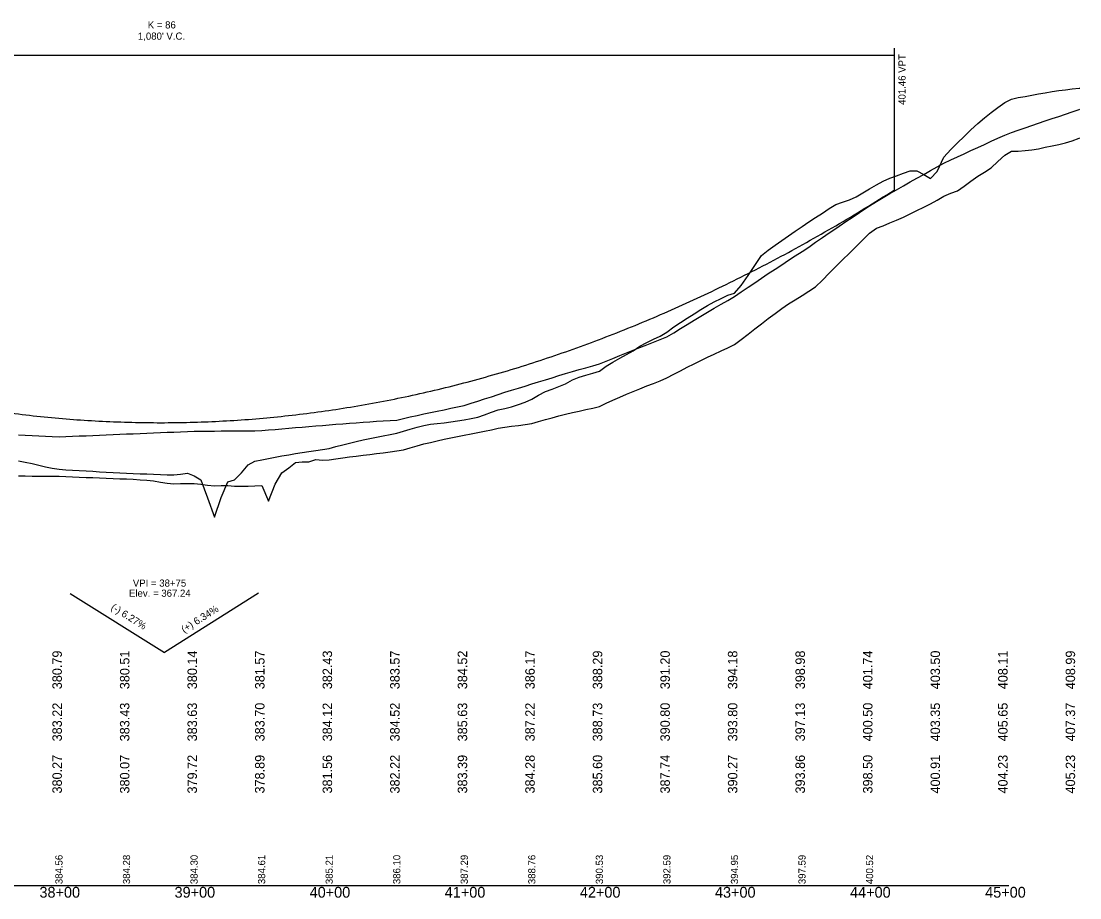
# Model space of a CAD drawing. Extents: x 2116146 to 2121546, y 979095 to 984095.
# Drawn here: x 2119138 to 2119922, y 981586 to 982235 of the extents above; entities that cross this region are included whole.
import ezdxf

# ---------------------------------------------------------------- set-up
doc = ezdxf.new("R2010")
doc.units = 0
for name, color, linetype in [('RD_DDB_GradeTX', 7, 'Continuous'), ('RD_DDB_Profile_EX', 7, 'Continuous'), ('RD_DDB_Profile_Lbl', 7, 'Continuous'), ('RD_DDB_Profile_PR', 7, 'Continuous'), ('RD_DDB_StaTX', 7, 'Continuous'), ('RD_DDB_StripGrade', 7, 'Continuous'), ('RD_DDB_VCLbl', 7, 'Continuous'), ('RD_GPK_Profile_Cell', 7, 'Continuous'), ('RD_Sketch2', 7, 'Continuous')]:
    doc.layers.add(name, color=color, linetype=linetype)

msp = doc.modelspace()

# ---------------------------------------------------------------- linework, layer by layer
at = {"layer": 'RD_DDB_GradeTX'}
for p in [(2119174.3, 981811.6), (2119313.72, 981811.95)]:
    msp.add_line(p, (2119244.12, 981767.84), dxfattribs=at)
at = {"layer": 'RD_DDB_Profile_EX'}
for points in [[(2119756.02, 982091.92), (2119761.02, 982095.22), (2119766.02, 982098.49), (2119771.02, 982101.66), (2119776.02, 982104.66), (2119781.02, 982107.56), (2119786.02, 982110.45), (2119791.02, 982113.32), (2119796.02, 982116.17), (2119801.02, 982118.99), (2119806.02, 982121.77), (2119811.02, 982124.56), (2119816.02, 982127.34), (2119821.02, 982130.05), (2119826.02, 982132.44), (2119831.02, 982134.77), (2119836.02, 982137.07), (2119841.02, 982139.36), (2119846.02, 982141.65), (2119851.02, 982144), (2119856.02, 982146.27), (2119861.02, 982148.49), (2119866.02, 982150.69), (2119871.02, 982152.8), (2119876.02, 982154.49), (2119881.02, 982156.22), (2119886.02, 982158.01), (2119891.02, 982159.79), (2119896.02, 982161.52), (2119901.02, 982163.11), (2119906.02, 982164.71), (2119911.02, 982166.42), (2119916.02, 982168.11), (2119921.02, 982169.77), (2119921.6, 982169.95)], [(2119256.02, 981931.31), (2119261.02, 981931.52), (2119266.02, 981931.74), (2119271.02, 981931.77), (2119276.02, 981931.8), (2119281.02, 981931.83), (2119286.02, 981931.87), (2119291.02, 981931.95), (2119296.02, 981931.98), (2119301.02, 981932.01), (2119306.02, 981932.03), (2119311.02, 981932.06), (2119316.02, 981932.15), (2119321.02, 981932.62), (2119326.02, 981933.09), (2119331.02, 981933.55), (2119336.02, 981934), (2119341.02, 981934.41), (2119346.02, 981934.75), (2119351.02, 981935.15), (2119356.02, 981935.56), (2119361.02, 981935.95), (2119366.02, 981936.36), (2119371.02, 981936.87), (2119376.02, 981937.24), (2119381.02, 981937.59), (2119386.02, 981937.94), (2119391.02, 981938.31), (2119396.02, 981938.76), (2119401.02, 981939.06), (2119406.02, 981939.35), (2119411.02, 981939.62), (2119416.02, 981939.98), (2119421.02, 981941.13), (2119426.02, 981942.26), (2119431.02, 981943.39), (2119436.02, 981944.5), (2119441.02, 981945.49), (2119446.02, 981946.57), (2119451.02, 981947.64), (2119456.02, 981948.7), (2119461.02, 981949.75), (2119466.02, 981950.71), (2119471.02, 981952.41), (2119476.02, 981954.03), (2119481.02, 981955.64), (2119486.02, 981957.24), (2119491.02, 981958.83), (2119496.02, 981960.48), (2119501.02, 981962.04), (2119506.02, 981963.59), (2119511.02, 981965.13), (2119516.02, 981966.67), (2119521.02, 981968.31), (2119526.02, 981969.82), (2119531.02, 981971.32), (2119536.02, 981972.81), (2119541.02, 981974.29), (2119546.02, 981975.84), (2119551.02, 981977.28), (2119556.02, 981978.7), (2119561.02, 981980.1), (2119566.02, 981981.49), (2119571.02, 981983.53), (2119576.02, 981985.6), (2119581.02, 981987.64), (2119586.02, 981989.67), (2119591.02, 981991.68), (2119596.02, 981993.67), (2119601.02, 981995.64), (2119606.02, 981997.6), (2119611.02, 981999.51), (2119616.02, 982001.53), (2119621.02, 982004.63), (2119626.02, 982007.7), (2119631.02, 982010.75), (2119636.02, 982013.78), (2119641.02, 982016.77), (2119646.02, 982019.75), (2119651.02, 982022.71), (2119656.02, 982025.65), (2119661.02, 982028.56), (2119666.02, 982031.41), (2119671.02, 982034.8), (2119676.02, 982038.23), (2119681.02, 982041.63), (2119686.02, 982045), (2119691.02, 982048.35), (2119696.02, 982051.62), (2119701.02, 982054.91), (2119706.02, 982058.18), (2119711.02, 982061.42), (2119716.02, 982064.63), (2119721.02, 982068.02), (2119726.02, 982071.52), (2119731.02, 982074.99), (2119736.02, 982078.43), (2119741.02, 982081.84), (2119746.02, 982085.23), (2119751.02, 982088.59), (2119756.02, 982091.92)], [(2119136.02, 981928.95), (2119141.02, 981928.7), (2119146.02, 981928.45), (2119151.02, 981928.2), (2119156.02, 981927.94), (2119161.02, 981927.69), (2119166.02, 981927.58), (2119171.02, 981927.78), (2119176.02, 981927.98), (2119181.02, 981928.19), (2119186.02, 981928.39), (2119191.02, 981928.61), (2119196.02, 981928.81), (2119201.02, 981929.01), (2119206.02, 981929.22), (2119211.02, 981929.42), (2119216.02, 981929.64), (2119221.02, 981929.85), (2119226.02, 981930.05), (2119231.02, 981930.26), (2119236.02, 981930.47), (2119241.02, 981930.69), (2119246.02, 981930.9), (2119251.02, 981931.1), (2119256.02, 981931.31)]]:
    msp.add_lwpolyline(points, dxfattribs=at)
at = {"layer": 'RD_DDB_Profile_PR'}
msp.add_spline([(2118704.12, 982106.3), (2118725.72, 982093.03), (2118747.32, 982080.31), (2118768.92, 982068.13), (2118790.52, 982056.5), (2118812.12, 982045.41), (2118833.72, 982034.87), (2118855.32, 982024.87), (2118876.92, 982015.42), (2118898.52, 982006.51), (2118920.12, 981998.14), (2118941.72, 981990.32), (2118963.32, 981983.05), (2118984.92, 981976.32), (2119006.52, 981970.13), (2119028.12, 981964.49), (2119049.72, 981959.39), (2119071.32, 981954.84), (2119092.92, 981950.83), (2119114.52, 981947.37), (2119136.12, 981944.45), (2119157.72, 981942.07), (2119179.32, 981940.24), (2119200.92, 981938.96), (2119222.52, 981938.22), (2119244.12, 981938.02), (2119265.72, 981938.37), (2119287.32, 981939.26), (2119308.92, 981940.7), (2119330.52, 981942.68), (2119352.12, 981945.21), (2119373.72, 981948.28), (2119395.32, 981951.89), (2119416.92, 981956.05), (2119438.52, 981960.76), (2119460.12, 981966.01), (2119481.72, 981971.8), (2119503.32, 981978.14), (2119524.92, 981985.03), (2119546.52, 981992.45), (2119568.12, 982000.43), (2119589.72, 982008.94), (2119611.32, 982018), (2119632.92, 982027.61), (2119654.52, 982037.76), (2119676.12, 982048.46), (2119697.72, 982059.7), (2119719.32, 982071.48), (2119740.92, 982083.81), (2119762.52, 982096.68), (2119784.12, 982110.1)], degree=3, dxfattribs=at)
at = {"layer": 'RD_DDB_VCLbl'}
for p, q in [((2119784.12, 982215.1), (2119784.12, 982110.1)), ((2118704.12, 982210.1), (2119784.12, 982210.1))]:
    msp.add_line(p, q, dxfattribs=at)
at = {"layer": 'RD_GPK_Profile_Cell'}
msp.add_line((2117569.12, 981595.48), (2119869.12, 981595.48), dxfattribs=at)
at = {"layer": 'RD_Sketch2'}
for points in [[(2119756.02, 982105.09), (2119761.02, 982108.15), (2119766.02, 982111.08), (2119771.02, 982113.99), (2119776.02, 982116.88), (2119781.02, 982119.01), (2119786.02, 982120.82), (2119791.02, 982122.68), (2119796.02, 982124.51), (2119801.02, 982124.49), (2119806.02, 982121.78), (2119811.02, 982118.63), (2119816.02, 982124.03), (2119821.02, 982134.49), (2119826.02, 982140.12), (2119831.02, 982145.1), (2119836.02, 982149.9), (2119841.02, 982154.79), (2119846.02, 982159.53), (2119851.02, 982163.63), (2119856.02, 982167.56), (2119861.02, 982171.31), (2119866.02, 982174.89), (2119871.02, 982177.54), (2119876.02, 982178.56), (2119881.02, 982179.52), (2119886.02, 982180.42), (2119891.02, 982181.27), (2119896.02, 982182.2), (2119901.02, 982183.06), (2119906.02, 982183.77), (2119911.02, 982184.42), (2119916.02, 982185.01), (2119921.02, 982185.54), (2119921.52, 982185.58)], [(2119756.02, 982068.43), (2119761.02, 982073.35), (2119766.02, 982078.22), (2119771.02, 982081.9), (2119776.02, 982083.82), (2119781.02, 982085.81), (2119786.02, 982087.87), (2119791.02, 982090.22), (2119796.02, 982092.67), (2119801.02, 982095.02), (2119806.02, 982097.44), (2119811.02, 982099.93), (2119816.02, 982102.77), (2119821.02, 982105.62), (2119826.02, 982107.76), (2119831.02, 982109.72), (2119836.02, 982113.15), (2119841.02, 982116.81), (2119846.02, 982120.56), (2119851.02, 982123.43), (2119856.02, 982126.69), (2119861.02, 982131.22), (2119866.02, 982135.9), (2119871.02, 982138.88), (2119876.02, 982139.05), (2119881.02, 982139.37), (2119886.02, 982139.84), (2119891.02, 982140.6), (2119896.02, 982141.96), (2119901.02, 982142.89), (2119906.02, 982143.94), (2119911.02, 982145.1), (2119916.02, 982146.58), (2119921.02, 982148.59), (2119921.6, 982148.78)], [(2119256.02, 981899.83), (2119261.02, 981900.68), (2119266.02, 981898.75), (2119271.02, 981895.8), (2119276.02, 981882.44), (2119281.02, 981868.19), (2119286.02, 981882.57), (2119291.02, 981894.21), (2119296.02, 981895.65), (2119301.02, 981900.82), (2119306.02, 981906.79), (2119311.02, 981909.64), (2119316.02, 981910.6), (2119321.02, 981911.6), (2119326.02, 981912.57), (2119331.02, 981913.47), (2119336.02, 981914.31), (2119341.02, 981915.15), (2119346.02, 981916), (2119351.02, 981916.79), (2119356.02, 981917.5), (2119361.02, 981918.18), (2119366.02, 981918.96), (2119371.02, 981920.28), (2119376.02, 981921.56), (2119381.02, 981922.82), (2119386.02, 981924.06), (2119391.02, 981925.2), (2119396.02, 981926.23), (2119401.02, 981927.26), (2119406.02, 981928.29), (2119411.02, 981929.3), (2119416.02, 981930.34), (2119421.02, 981931.76), (2119426.02, 981933.18), (2119431.02, 981934.6), (2119436.02, 981936.01), (2119441.02, 981936.8), (2119446.02, 981937.44), (2119451.02, 981938.01), (2119456.02, 981938.53), (2119461.02, 981939.3), (2119466.02, 981940.03), (2119471.02, 981941.15), (2119476.02, 981942.21), (2119481.02, 981943.92), (2119486.02, 981945.85), (2119491.02, 981947.56), (2119496.02, 981948.57), (2119501.02, 981949.67), (2119506.02, 981951.47), (2119511.02, 981953.25), (2119516.02, 981955.31), (2119521.02, 981958.33), (2119526.02, 981960.97), (2119531.02, 981962.86), (2119536.02, 981964.7), (2119541.02, 981966.87), (2119546.02, 981969.68), (2119551.02, 981971.62), (2119556.02, 981973.15), (2119561.02, 981974.6), (2119566.02, 981976.11), (2119571.02, 981979.75), (2119576.02, 981982.91), (2119581.02, 981985.75), (2119586.02, 981988.51), (2119591.02, 981991.26), (2119596.02, 981994.64), (2119601.02, 981997.42), (2119606.02, 981999.78), (2119611.02, 982002.03), (2119616.02, 982004.98), (2119621.02, 982008.93), (2119626.02, 982012.24), (2119631.02, 982015.44), (2119636.02, 982018.5), (2119641.02, 982021.76), (2119646.02, 982024.77), (2119651.02, 982027.43), (2119656.02, 982029.96), (2119661.02, 982032.36), (2119666.02, 982033.83), (2119671.02, 982039.44), (2119676.02, 982046.85), (2119681.02, 982054.27), (2119686.02, 982061.67), (2119691.02, 982065.74), (2119696.02, 982069.29), (2119701.02, 982072.82), (2119706.02, 982076.32), (2119711.02, 982079.79), (2119716.02, 982083.23), (2119721.02, 982086.58), (2119726.02, 982089.88), (2119731.02, 982093.16), (2119736.02, 982096.41), (2119741.02, 982099.61), (2119746.02, 982101.29), (2119751.02, 982102.96), (2119756.02, 982105.09)], [(2119256.02, 981892.95), (2119261.02, 981893.09), (2119266.02, 981893.07), (2119271.02, 981892.39), (2119276.02, 981891.71), (2119281.02, 981891.38), (2119286.02, 981891.52), (2119291.02, 981891.55), (2119296.02, 981891.13), (2119301.02, 981890.91), (2119306.02, 981891.09), (2119311.02, 981891.27), (2119316.02, 981891.44), (2119321.02, 981879.98), (2119326.02, 981892.53), (2119331.02, 981900.8), (2119336.02, 981904.62), (2119341.02, 981908.44), (2119346.02, 981909.04), (2119351.02, 981909.16), (2119356.02, 981910.88), (2119361.02, 981910.36), (2119366.02, 981910.64), (2119371.02, 981911.32), (2119376.02, 981911.98), (2119381.02, 981912.63), (2119386.02, 981913.28), (2119391.02, 981913.95), (2119396.02, 981914.57), (2119401.02, 981915.19), (2119406.02, 981915.8), (2119411.02, 981916.41), (2119416.02, 981917.11), (2119421.02, 981917.99), (2119426.02, 981919.47), (2119431.02, 981920.91), (2119436.02, 981922.27), (2119441.02, 981923.35), (2119446.02, 981924.58), (2119451.02, 981925.76), (2119456.02, 981926.89), (2119461.02, 981927.85), (2119466.02, 981928.75), (2119471.02, 981929.75), (2119476.02, 981930.71), (2119481.02, 981931.63), (2119486.02, 981932.67), (2119491.02, 981934.01), (2119496.02, 981934.74), (2119501.02, 981935.4), (2119506.02, 981936.02), (2119511.02, 981936.58), (2119516.02, 981937.35), (2119521.02, 981938.87), (2119526.02, 981940.32), (2119531.02, 981941.72), (2119536.02, 981943.05), (2119541.02, 981944.31), (2119546.02, 981945.51), (2119551.02, 981946.64), (2119556.02, 981947.71), (2119561.02, 981948.72), (2119566.02, 981949.98), (2119571.02, 981952.35), (2119576.02, 981954.66), (2119581.02, 981956.9), (2119586.02, 981959.08), (2119591.02, 981961.11), (2119596.02, 981963.17), (2119601.02, 981965.18), (2119606.02, 981967.11), (2119611.02, 981968.99), (2119616.02, 981971.21), (2119621.02, 981973.88), (2119626.02, 981976.5), (2119631.02, 981979.06), (2119636.02, 981981.56), (2119641.02, 981984.05), (2119646.02, 981986.42), (2119651.02, 981988.72), (2119656.02, 981991.09), (2119661.02, 981993.51), (2119666.02, 981995.97), (2119671.02, 981999.51), (2119676.02, 982003.48), (2119681.02, 982007.38), (2119686.02, 982011.23), (2119691.02, 982015.02), (2119696.02, 982018.75), (2119701.02, 982022.41), (2119706.02, 982026.02), (2119711.02, 982029.04), (2119716.02, 982032.02), (2119721.02, 982035.37), (2119726.02, 982038.67), (2119731.02, 982043.52), (2119736.02, 982048.57), (2119741.02, 982053.59), (2119746.02, 982058.58), (2119751.02, 982063.55), (2119756.02, 982068.43)], [(2119136.02, 981909.85), (2119141.02, 981908.82), (2119146.02, 981907.69), (2119151.02, 981906.57), (2119156.02, 981905.44), (2119161.02, 981904.43), (2119166.02, 981903.6), (2119171.02, 981903.22), (2119176.02, 981902.83), (2119181.02, 981902.56), (2119186.02, 981902.33), (2119191.02, 981902.06), (2119196.02, 981901.69), (2119201.02, 981901.4), (2119206.02, 981901.19), (2119211.02, 981900.98), (2119216.02, 981900.74), (2119221.02, 981900.42), (2119226.02, 981900.24), (2119231.02, 981900.05), (2119236.02, 981899.87), (2119241.02, 981899.65), (2119246.02, 981899.47), (2119251.02, 981899.31), (2119256.02, 981899.83)], [(2119136.02, 981898.68), (2119141.02, 981898.71), (2119146.02, 981898.43), (2119151.02, 981898.32), (2119156.02, 981898.35), (2119161.02, 981898.38), (2119166.02, 981898.33), (2119171.02, 981898.1), (2119176.02, 981897.87), (2119181.02, 981897.64), (2119186.02, 981897.47), (2119191.02, 981897.46), (2119196.02, 981897.21), (2119201.02, 981896.96), (2119206.02, 981896.7), (2119211.02, 981896.45), (2119216.02, 981896.37), (2119221.02, 981896.09), (2119226.02, 981895.81), (2119231.02, 981895.53), (2119236.02, 981895.02), (2119241.02, 981894.1), (2119246.02, 981893.19), (2119251.02, 981892.81), (2119256.02, 981892.95)]]:
    msp.add_lwpolyline(points, dxfattribs=at)

# ---------------------------------------------------------------- texts
at = {"layer": 'RD_DDB_GradeTX'}
for s, rotation, p in [('(-) 6.27%', 327.92167, (2119203.95, 981800.07)), ('(+) 6.34%', 32.36701, (2119258.55, 981782.23))]:
    msp.add_text(s, height=5.312, rotation=rotation, dxfattribs=at).set_placement(p)
at = {"layer": 'RD_DDB_Profile_Lbl'}
for s, p in [('VPI = 38+75', (2119220.66, 981816.64)), ('Elev. = 367.24', (2119217.84, 981809.16))]:
    msp.add_text(s, height=5.312, dxfattribs=at).set_placement(p)
at = {"layer": 'RD_DDB_StaTX'}
for s, p in [('38+00', (2119151.53, 981586.48)), ('39+00', (2119251.53, 981586.48)), ('40+00', (2119351.53, 981586.48)), ('41+00', (2119451.53, 981586.48)), ('42+00', (2119551.53, 981586.48)), ('43+00', (2119651.53, 981586.48)), ('44+00', (2119751.53, 981586.48)), ('45+00', (2119851.53, 981586.48))]:
    msp.add_text(s, height=8, dxfattribs=at).set_placement(p)
at = {"layer": 'RD_DDB_StripGrade'}
for s, height, p in [('401.46 VPT', 5.312, (2119792.62, 982173.23)), ('383.22', 7, (2119168.12, 981702.15)), ('383.43', 7, (2119218.12, 981702.15)), ('383.63', 7, (2119268.12, 981702.15)), ('383.70', 7, (2119318.12, 981702.15)), ('384.12', 7, (2119368.12, 981702.15)), ('384.52', 7, (2119418.12, 981702.15)), ('385.63', 7, (2119468.12, 981702.15)), ('387.22', 7, (2119518.12, 981702.15)), ('388.73', 7, (2119568.12, 981702.15)), ('390.80', 7, (2119618.12, 981702.15)), ('393.80', 7, (2119668.12, 981702.15)), ('397.13', 7, (2119718.12, 981702.15)), ('400.50', 7, (2119768.12, 981702.15)), ('403.35', 7, (2119818.12, 981702.15)), ('405.65', 7, (2119868.12, 981702.15)), ('407.37', 7, (2119918.12, 981702.15)), ('384.56', 5.312, (2119168.62, 981596.48)), ('384.28', 5.312, (2119218.62, 981596.48)), ('384.30', 5.312, (2119268.62, 981596.48)), ('384.61', 5.312, (2119318.62, 981596.48)), ('385.21', 5.312, (2119368.62, 981596.48)), ('386.10', 5.312, (2119418.62, 981596.48)), ('387.29', 5.312, (2119468.62, 981596.48)), ('388.76', 5.312, (2119518.62, 981596.48)), ('390.53', 5.312, (2119568.62, 981596.48)), ('392.59', 5.312, (2119618.62, 981596.48)), ('394.95', 5.312, (2119668.62, 981596.48)), ('397.59', 5.312, (2119718.62, 981596.48)), ('400.52', 5.312, (2119768.62, 981596.48))]:
    msp.add_text(s, height=height, rotation=90, dxfattribs=at).set_placement(p)
at = {"layer": 'RD_DDB_VCLbl'}
for s, p in [('K = 86', (2119231.72, 982229.77)), ("1,080' V.C.", (2119224.4, 982221.45))]:
    msp.add_text(s, height=5.312, dxfattribs=at).set_placement(p)
at = {"layer": 'RD_Sketch2'}
for s, p in [('380.79', (2119168.12, 981740.73)), ('380.51', (2119218.12, 981740.73)), ('380.14', (2119268.12, 981740.73)), ('381.57', (2119318.12, 981740.73)), ('382.43', (2119368.12, 981740.73)), ('383.57', (2119418.12, 981740.73)), ('384.52', (2119468.12, 981740.73)), ('386.17', (2119518.12, 981740.73)), ('388.29', (2119568.12, 981740.73)), ('391.20', (2119618.12, 981740.73)), ('394.18', (2119668.12, 981740.73)), ('398.98', (2119718.12, 981740.73)), ('401.74', (2119768.12, 981740.73)), ('403.50', (2119818.12, 981740.73)), ('408.11', (2119868.12, 981740.73)), ('408.99', (2119918.12, 981740.73)), ('380.27', (2119168.12, 981663.56)), ('380.07', (2119218.12, 981663.56)), ('379.72', (2119268.12, 981663.56)), ('378.89', (2119318.12, 981663.56)), ('381.56', (2119368.12, 981663.56)), ('382.22', (2119418.12, 981663.56)), ('383.39', (2119468.12, 981663.56)), ('384.28', (2119518.12, 981663.56)), ('385.60', (2119568.12, 981663.56)), ('387.74', (2119618.12, 981663.56)), ('390.27', (2119668.12, 981663.56)), ('393.86', (2119718.12, 981663.56)), ('398.50', (2119768.12, 981663.56)), ('400.91', (2119818.12, 981663.56)), ('404.23', (2119868.12, 981663.56)), ('405.23', (2119918.12, 981663.56))]:
    msp.add_text(s, height=7, rotation=90, dxfattribs=at).set_placement(p)

doc.saveas('drawing.dxf')
